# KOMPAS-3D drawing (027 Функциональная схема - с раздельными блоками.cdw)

Referenced files in D:\prfiles\Libs\Ventilation\: Projects
Referenced files: SPDS_GR.LYT, SPDS.tdp
Referenced files in \\PROMSRV3\DocSbyt\_ОБЩИЕ ДОКУМЕНТЫ\СПС\002_Проекты (ПСПД)\г. Елабуга\ПСПД-0173-2012 строителей 13\: 040_Принципиальная схема -.cdw
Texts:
  ПСПД-0000-2015
  Атрибуты проекта
  Должность
  Фамилия
  Атрибуты слоя
  Марка/позиционное обозначение без линии-выноски
  Normal
  TPI
  - преобразователь расхода;
  - термопреобразователь;
  Приборы
  По месту (на
  трубопроводе)
  На щите (в
  ТВ7-04)
  - тепловычислитель
  - блок автоматический регистрационно-связной БАРС;
  - датчик давления;
  ТPI
  - термоманометр;
  Узел учета
  Ду65
  Ду50
  из СО
  в СО
  Подающий трубопровод
  отопления
  Обратный трубопровод
  (0-1,6 МПа, 0-150 С)
  (0-1,6 МПа)
  Кран проходной
  Направление потока жидкости
  Кран трёхходовой
  Муфта свертная
  Клапан трёхходовой
  Фильтр
  Клапан обратный проходной
  Переход
  Задвижка
  01 Спецификация. ГОСТ 21.101-97 Ф7
  Спецификация. Первый лист. ГОСТ 21.101-97 Ф7
  Лит-Масса-Масштаб
  Материал-Предприятие
  Title Specification
  Body Specification ( left align )
  Body Specificaton ( centered )
  Поз.
  Кол.
  ед., кг
  Приме-
  чание
  Обозначение позиции (марки) элементов конструкций, установок
  Обозначение основных документов на эл. конструкци, оборудование и изделия.
  Наименование элементов конструкций, оборудования, изделий и их марки.
  Количество элементов
  Масса в килограммах (тоннах с указанием ед.изм.)
  Дополнительные сведения
  Таблица спецификации
  ЗАО "ПромСервис"
  тепловой энергии, теплоносителя
  ГИП
  Пров.
  Разраб.
  Функциональная схема
  Рабоч. чертеж зданий и сооруж. ГОСТ Р 21.1101-2009 Ф3.
  Стадия
  Лист
  Листов
  Изм.
  Кол.уч.
  №док.
  Подп.
  Дата
  Изменение
  Номер документа
  Подпись
  Обозначение документа
  Наименование предприятия, в состав которого входит здание (сооружение)
  Наименование здания (сооружения)
  Порядковый номер листа
  Количество листов в документе
  Должность подписавшего
  Наименование изображения
  Индекс предприятия, выпускающего документ
  Инв. № подл.
  Подп. и дата
  Взам. инв. №
  Инвентарный номер подлинника
  Подпись принявшего подлинник на хранение
  Инвентарный номер подлинника, взамен которого выпущен данный подлинник
  Согласовано
  Согласование
  Рабоч. чертеж зданий и сооруж. ГОСТ 21.101-97 Ф3.
Dimensions and other numbers on the sheet: 0; 1; 2; 4; 3; 6; 5; 7; 8; 10; 11; 12; 24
